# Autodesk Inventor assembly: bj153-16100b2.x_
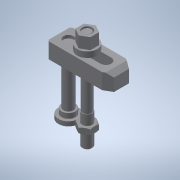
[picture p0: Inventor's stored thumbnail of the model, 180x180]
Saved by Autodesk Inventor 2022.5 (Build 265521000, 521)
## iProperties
Part Number: bj153-16100b2.x_
Material: 一般
Document SubType Name: Assembly
Designer: ImaoCorp
Sending System: SOLIDWORKS 2017-2017317
MC: AMD64
MC_MODEL: Intel64 Family 6 Model 60 Stepping 3, GenuineIntel
OS: Windows_NT
FRU: Parasolid Version 29.0, build 201,  4-17-2017
FORMAT: text
GUISE: transmit
KEY: bj153-16100b2
FILE: bj153-16100b2.x_t
DATE: Fri Mar 15 10:23:34 2019
Author: ImaoCorp
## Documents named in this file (6)
- X:\14_SW2022-Inv2022\00_全2023-1023新製品(TCC)まで\b\bj153-16100b2\BJ153-16100B2.iam
- X:\14_SW2022-Inv2022\00_全2023-1023新製品(TCC)まで\b\bj153-16100b2\bj153-16100b2_01.ipt
- X:\14_SW2022-Inv2022\00_全2023-1023新製品(TCC)まで\b\bj153-16100b2\bj153-16100b2_02.ipt
- X:\14_SW2022-Inv2022\00_全2023-1023新製品(TCC)まで\b\bj153-16100b2\bj153-16100b2_03.ipt
- X:\14_SW2022-Inv2022\00_全2023-1023新製品(TCC)まで\b\bj153-16100b2\bj153-16100b2_04.ipt
- X:\14_SW2022-Inv2022\00_全2023-1023新製品(TCC)まで\b\bj153-16100b2\bj153-16100b2_05.ipt
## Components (5 placed, 5 different names)
1. bj153-16100b2_01
2. bj153-16100b2_02
3. bj153-16100b2_03
4. bj153-16100b2_04
5. bj153-16100b2_05
